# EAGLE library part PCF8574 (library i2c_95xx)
Remote 8-Bit I/O Expander for I²C Bus
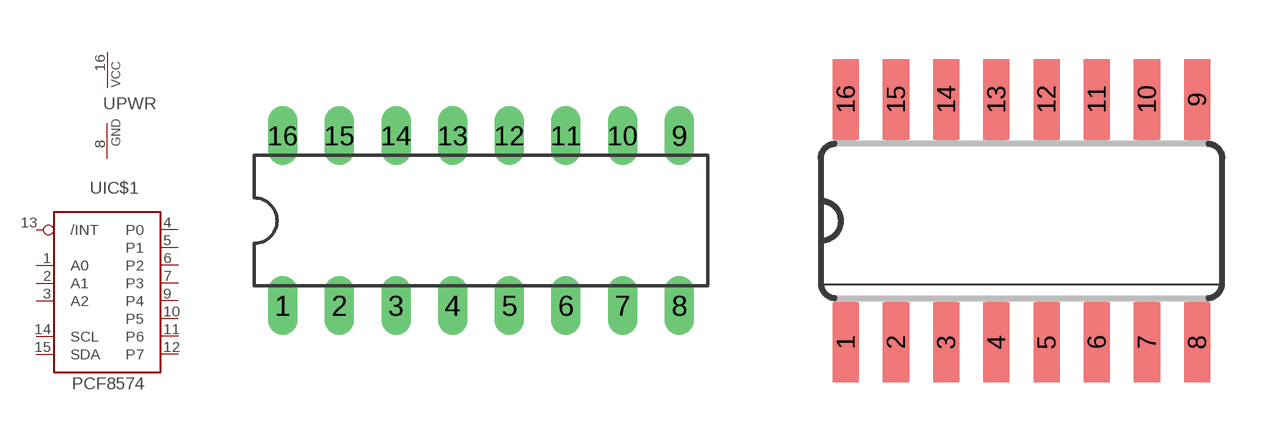
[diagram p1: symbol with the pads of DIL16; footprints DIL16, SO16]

Designator prefix -; gates IC$1=PCF8574 PWR=PWRN

## PCF8574P  [DIL16]
1  IC$1:A0  in
2  IC$1:A1  in
3  IC$1:A2  in
4  IC$1:P0
5  IC$1:P1
6  IC$1:P2
7  IC$1:P3
8  PWR:GND  pwr
9  IC$1:P4
10  IC$1:P5
11  IC$1:P6
12  IC$1:P7
13  IC$1:/INT  out
14  IC$1:SCL  in
15  IC$1:SDA
16  PWR:VCC  pwr

## PCF8574AP  [DIL16]
Pads as for DIL16

## PCF8574T  [SO16]
Pads as for DIL16

## PCF8574AT  [SO16]
Pads as for DIL16

## Footprint DIL16 (pad centres in mm)
drill 0.813 long: 1 -8.89,-3.81; 2 -6.35,-3.81; 3 -3.81,-3.81; 4 -1.27,-3.81; 5 1.27,-3.81; 6 3.81,-3.81; 7 6.35,-3.81; 8 8.89,-3.81; 9 8.89,3.81; 10 6.35,3.81; 11 3.81,3.81; 12 1.27,3.81; 13 -1.27,3.81; 14 -3.81,3.81; 15 -6.35,3.81; 16 -8.89,3.81

## Footprint SO16 (pad centres in mm)
smd 0.66 x 2.032: 1 -4.445,-3.073; 2 -3.175,-3.073; 3 -1.905,-3.073; 4 -0.635,-3.073; 5 0.635,-3.073; 6 1.905,-3.073; 7 3.175,-3.073; 8 4.445,-3.073; 9 4.445,3.073; 10 3.175,3.073; 11 1.905,3.073; 12 0.635,3.073; 13 -0.635,3.073; 14 -1.905,3.073; 15 -3.175,3.073; 16 -4.445,3.073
